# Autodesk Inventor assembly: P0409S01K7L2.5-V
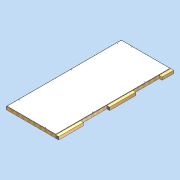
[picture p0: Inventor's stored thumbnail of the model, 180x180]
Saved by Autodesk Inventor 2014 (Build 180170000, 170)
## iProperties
Created: 2011-04
Part Number: P0409S01K7L2.5-V
Document SubType Name: Assembly
Designer: david.appleford
Description: 1w x 2.25w  01 Panel - 7 Locks 2.5 Lugs
Mass: 48000 g
Surface Area: 72046.9 cm^2
Volume: 252510 cm^3
Density: 0.190092 g/cm^3
Cost Center: £161.00
Justset: False
Title: 1w x 2.25w  01 Panel - 7 Locks 2.5 Lugs
Author: david.appleford
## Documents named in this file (5)
- C:\Documents and Settings\john.everitt\Local Settings\My Documents\Vault\Production MkII\VIRTUAL ELEMENTS\Virtual Walls\Virtual Timber + MgO\P0409S01K7L2.5-V.iam
- C:\Documents and Settings\john.everitt\Local Settings\My Documents\Vault\Production MkII\VIRTUAL ELEMENTS\Virtual Lugs\Superceded Lugs\LA02C3V.ipt
- C:\Documents and Settings\john.everitt\Local Settings\My Documents\Vault\Production MkII\VIRTUAL ELEMENTS\Virtual Lugs\Superceded Lugs\LA02M3V.ipt
- C:\Documents and Settings\john.everitt\Local Settings\My Documents\Vault\Production MkII\Virtual Elements\Virtual Walls\Virtual Timber + MgO\P0409S01K7-V.ipt
- C:\Documents and Settings\john.everitt\Local Settings\My Documents\Vault\Production MkII\VIRTUAL ELEMENTS\Virtual Lugs\Superceded Lugs\LA01C3V.ipt
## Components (4 placed, 4 different names)
1. P0409S01K7-V:1 — Mate:1, Flush:1, Flush:2, Mate:7, Flush:11, Mate:14, Flush:12, Flush:13
2. LA02C3V:1 — Mate:1, Flush:1, Flush:2, Mate:9
3. LA02M3V:4 — Mate:7, Flush:11, Mate:9
4. LA01C3V:1 — Mate:14, Flush:12, Flush:13
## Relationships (9: Flush 5, Mate 4)
- Mate:1: P0409S01K7-V:1 ↔ LA02C3V:1
- Flush:1: P0409S01K7-V:1 ↔ LA02C3V:1
- Flush:2: P0409S01K7-V:1 ↔ LA02C3V:1
- Mate:7: P0409S01K7-V:1 ↔ LA02M3V:4
- Flush:11: P0409S01K7-V:1 ↔ LA02M3V:4
- Mate:9: LA02C3V:1 ↔ LA02M3V:4
- Mate:14: P0409S01K7-V:1 ↔ LA01C3V:1
- Flush:12: P0409S01K7-V:1 ↔ LA01C3V:1
- Flush:13: P0409S01K7-V:1 ↔ LA01C3V:1
## Named parameters: t = 1 mm, Cl = 2 mm
